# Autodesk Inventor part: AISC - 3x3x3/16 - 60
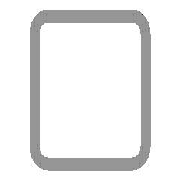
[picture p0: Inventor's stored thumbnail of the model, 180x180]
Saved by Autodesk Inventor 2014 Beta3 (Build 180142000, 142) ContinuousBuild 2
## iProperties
IsCustomPart: 1
Created: 2010-11
Part Number: AISC - 3x3x3/16 - 60
Material: Steel, Mild
Description: Tube
Document SubType Name: Modeling
Standard: ANSI
Designer: Beta-8540w
Standards Organization: ANSI
Language: en-US
Size Designation: 3x3x3/16
Categories: <MemberInstance><Categories><Category DisplayName="Structural Shapes" InternalName="089c4875-fa83-4c05-b084-43b9cc11f5ed" Mnemonic="GRDR"><CategoryParameter Dis
Stock Number: 3x3x3/16
Density: 7.86 g/cm^3
Appearance: Steel
_CCFamilyMember: 9
_CCFamilyDisplayName: ANSI AISC (Square) - Tube
_FrameMemberDoc: Frame Member File
_Version: 15.0.0
_GetPNFromCC: 1
G_L: 60.000 in
G_W: 3.000 in
G_H: 3.000 in
Author: Beta-8540w
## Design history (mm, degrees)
node "Start plane"
node "End plane"
sketch "Sketch"
  geometry: L1 (-38.1, -28.575)-(-38.1, 28.575); L2 (-28.575, 38.1)-(28.575, 38.1); L3 (38.1, 28.575)-(38.1, -28.575); L4 (28.575, -38.1)-(-28.575, -38.1); L5 (-28.575, 33.337)-(28.575, 33.338); L6 (33.338, 28.575)-(33.338, -28.575); L7 (28.575, -33.337)-(-28.575, -33.338); L8 (-33.338, -28.575)-(-33.338, 28.575); L9 (0, 56.102)-(0, -56.102) reference; L10 (-56.102, 0)-(56.102, 0) reference; A1 r 9.525 centre (-28.575, -28.575) between (-38.1, -28.575) and (-28.575, -38.1); A2 r 9.525 centre (-28.575, 28.575) between (-28.575, 38.1) and (-38.1, 28.575); A3 r 9.525 centre (28.575, 28.575) between (38.1, 28.575) and (28.575, 38.1); A4 r 9.525 centre (28.575, -28.575) between (28.575, -38.1) and (38.1, -28.575); A5 r 4.763 centre (-28.575, 28.575) between (-28.575, 33.337) and (-33.338, 28.575); A6 r 4.763 centre (28.575, 28.575) between (33.338, 28.575) and (28.575, 33.338); A7 r 4.763 centre (28.575, -28.575) between (28.575, -33.337) and (33.338, -28.575); A8 r 4.763 centre (-28.575, -28.575) between (-33.338, -28.575) and (-28.575, -33.338)
  constraints: 16 end point, 16 point on circle, 8 centre point, 8 tangent, 4 parallel, 3 equal radius, 2 perpendicular, 7 other
  dimensions: "d10" = 76.2 distance between parallel lines of L2 L4 (= G_H); "d11" = 76.2 distance between parallel lines of L1 L3 (= G_W); "d12" = 4.7625 distance between parallel lines of L3 L6 (= G_T); "d15" = 38.1 distance between parallel lines of L2 L10 (= 0.5 x d10); "d16" = 38.1 distance between parallel lines of L9 L3 (= 0.5 x d11); "d17" = 9.525 radius of A1 (= G_IR)
extrude "Body" new body sketch "Sketch" stored distance "d3" = 1524 (= G_L); taper "d4" = 0 deg
node "Driven Length"
  sketch "Sketch3"
    geometry: L1 (0, 0)-(10, 0) reference
    constraints: 2 end point, 1 horizontal
  workplane "Work Plane3"
  sketch "Sketch4"
    geometry: L1 (-2, 0)-(12, 0) reference; L2 (-2, 1524)-(12, 1524) reference
    dimensions: "d19" = 1524 distance between parallel lines of L1 L2 (derived)
body "Solid1"
other parameters: "G_W" = 76.2 [user parameter; used in 1 equation term], "G_H" = 76.2 [user parameter; used in 1 equation term], "G_T" = 4.7625 [user parameter; used in 1 equation term], "G_IR" = 9.525 [user parameter; used in 1 equation term], "G_L" = 1524 (= d19) [user parameter; used in 1 equation term], "G_OFFSET_START" = 0 [user parameter; used in 1 equation term], "G_OFFSET_END" = 0 [user parameter; used in 1 equation term], "d13" = 0 (computed from G_OFFSET_START), "d14" = 1524 (= G_OFFSET_END + B_L), "B_L" = 1524 [user parameter; used in 1 equation term], "d18" = 90 deg
